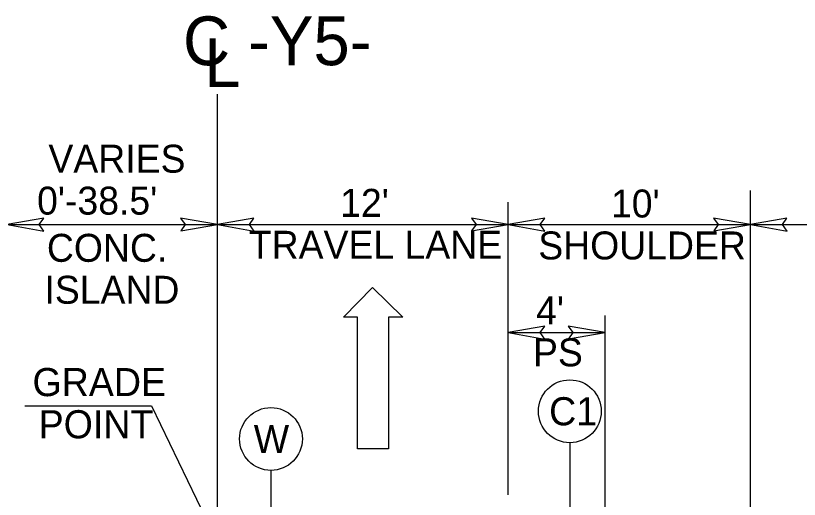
# Model space of a CAD drawing. Extents: x 2176156 to 2177167, y 76401 to 76644.
# Drawn here: x 2177099.84 to 2177132.18, y 76517.41 to 76537.36 of the extents above; entities that cross this region are included whole.
import ezdxf

# ---------------------------------------------------------------- set-up
doc = ezdxf.new("R2010")
doc.units = 0
for name, color, linetype in [('Exist Structure Minor Culvert Topo', 7, 'Continuous'), ('Exist Structure Minor Drop Inlet', 7, 'Continuous'), ('Exist Vegetation Woods Line', 7, 'Continuous'), ('Old_Level_1', 7, 'Continuous'), ('Old_Level_3', 7, 'Continuous'), ('Prop North Arrow NAD83 for Plan Sheets CELL', 7, 'Continuous')]:
    doc.layers.add(name, color=color, linetype=linetype)

msp = doc.modelspace()

# ---------------------------------------------------------------- linework, layer by layer
at = {"layer": 'Exist Structure Minor Drop Inlet'}
for p, q in [((2177113.369, 76524.92), (2177114.571, 76526.142)), ((2177114.571, 76526.142), (2177115.813, 76524.92)), ((2177113.951, 76524.92), (2177113.369, 76524.92)), ((2177113.951, 76519.488), (2177113.951, 76524.92)), ((2177115.813, 76524.92), (2177115.231, 76524.92)), ((2177115.231, 76524.92), (2177115.231, 76519.488)), ((2177115.231, 76519.488), (2177113.951, 76519.488))]:
    msp.add_line(p, q, dxfattribs=at)
at = {"layer": 'Old_Level_1'}
for points in [[(2177100.998, 76529.004), (2177099.488, 76528.744), (2177101.006, 76528.476), (2177100.813, 76528.744)], [(2177106.654, 76528.484), (2177108.163, 76528.744), (2177106.645, 76529.012), (2177106.838, 76528.744)], [(2177109.673, 76529.004), (2177108.163, 76528.744), (2177109.681, 76528.476), (2177109.489, 76528.744)], [(2177118.654, 76528.484), (2177120.163, 76528.744), (2177118.645, 76529.012), (2177118.838, 76528.744)], [(2177121.673, 76529.004), (2177120.163, 76528.744), (2177121.681, 76528.476), (2177121.489, 76528.744)], [(2177128.654, 76528.484), (2177130.163, 76528.744), (2177128.645, 76529.012), (2177128.838, 76528.744)], [(2177131.673, 76529.004), (2177130.163, 76528.744), (2177131.681, 76528.476), (2177131.489, 76528.744)], [(2177121.673, 76524.544), (2177120.163, 76524.284), (2177121.681, 76524.015), (2177121.489, 76524.284)], [(2177122.654, 76524.024), (2177124.163, 76524.284), (2177122.645, 76524.552), (2177122.838, 76524.284)]]:
    msp.add_lwpolyline(points, close=True, dxfattribs=at)
at = {"layer": 'Old_Level_3'}
for p, q in [((2177108.163, 76529.542), (2177108.163, 76534.127)), ((2177130.163, 76515.709), (2177130.163, 76530.14)), ((2177108.163, 76526.159), (2177108.163, 76529.542)), ((2177120.163, 76517.59), (2177120.163, 76529.672)), ((2177099.488, 76528.744), (2177108.163, 76528.744)), ((2177108.163, 76528.744), (2177120.057, 76528.744)), ((2177120.163, 76528.744), (2177130.163, 76528.744)), ((2177130.163, 76528.744), (2177142.163, 76528.744)), ((2177108.163, 76507.712), (2177108.163, 76526.159)), ((2177124.163, 76515.918), (2177124.163, 76524.993)), ((2177120.163, 76524.284), (2177124.163, 76524.284))]:
    msp.add_line(p, q, dxfattribs=at)
at = {"layer": 'Prop North Arrow NAD83 for Plan Sheets CELL'}
for p, q in [((2177100.221, 76521.259), (2177105.44, 76521.259)), ((2177105.44, 76521.259), (2177108.163, 76515.651)), ((2177122.711, 76519.744), (2177122.711, 76515.442)), ((2177110.374, 76518.601), (2177110.374, 76515.468))]:
    msp.add_line(p, q, dxfattribs=at)
for centre in [(2177122.711, 76521.04), (2177110.374, 76519.897)]:
    msp.add_circle(centre, 1.296, dxfattribs=at)

# ---------------------------------------------------------------- texts
at = {"layer": 'Exist Structure Minor Culvert Topo'}
for s, height, p in [('VARIES', 1.1533, (2177101.189, 76530.882)), ("0'-38.5'", 1.1533, (2177100.721, 76529.152)), ("12'", 1.1533, (2177113.231, 76529.06)), ("10' ", 1.1533, (2177124.41, 76529.033)), ('TRAVEL LANE', 1.15334, (2177109.461, 76527.33)), ('SHOULDER', 1.1533, (2177121.408, 76527.303)), ('CONC.', 1.1533, (2177101.126, 76527.205)), ('ISLAND', 1.1533, (2177101.025, 76525.475)), ("4' ", 1.1533, (2177121.319, 76524.625)), ('PS', 1.1533, (2177121.19, 76522.895))]:
    msp.add_text(s, height=height, dxfattribs=at).set_placement(p)
at = {"layer": 'Exist Vegetation Woods Line'}
msp.add_text('C -Y5- ', height=2.0131, dxfattribs=at).set_placement((2177106.743, 76535.315))
msp.add_text('L', height=2.013, rotation=359.9469, dxfattribs=at).set_placement((2177107.62, 76534.414))
at = {"layer": 'Prop North Arrow NAD83 for Plan Sheets CELL'}
for s, rotation, p in [('GRADE', 359.9998, (2177100.53, 76521.664)), ('C1', 359.9997, (2177121.855, 76520.46)), ('POINT', 359.9998, (2177100.783, 76519.924)), ('W', 359.9997, (2177109.662, 76519.317))]:
    msp.add_text(s, height=1.16, rotation=rotation, dxfattribs=at).set_placement(p)

doc.saveas('drawing.dxf')
